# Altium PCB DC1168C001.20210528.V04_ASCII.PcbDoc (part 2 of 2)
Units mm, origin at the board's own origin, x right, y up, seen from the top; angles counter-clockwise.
Board outline 94.98 x 78.49 mm, 2 copper layers (Top Layer, Bottom Layer); 113 components, 100 nets, 347 pads, 214 vias.
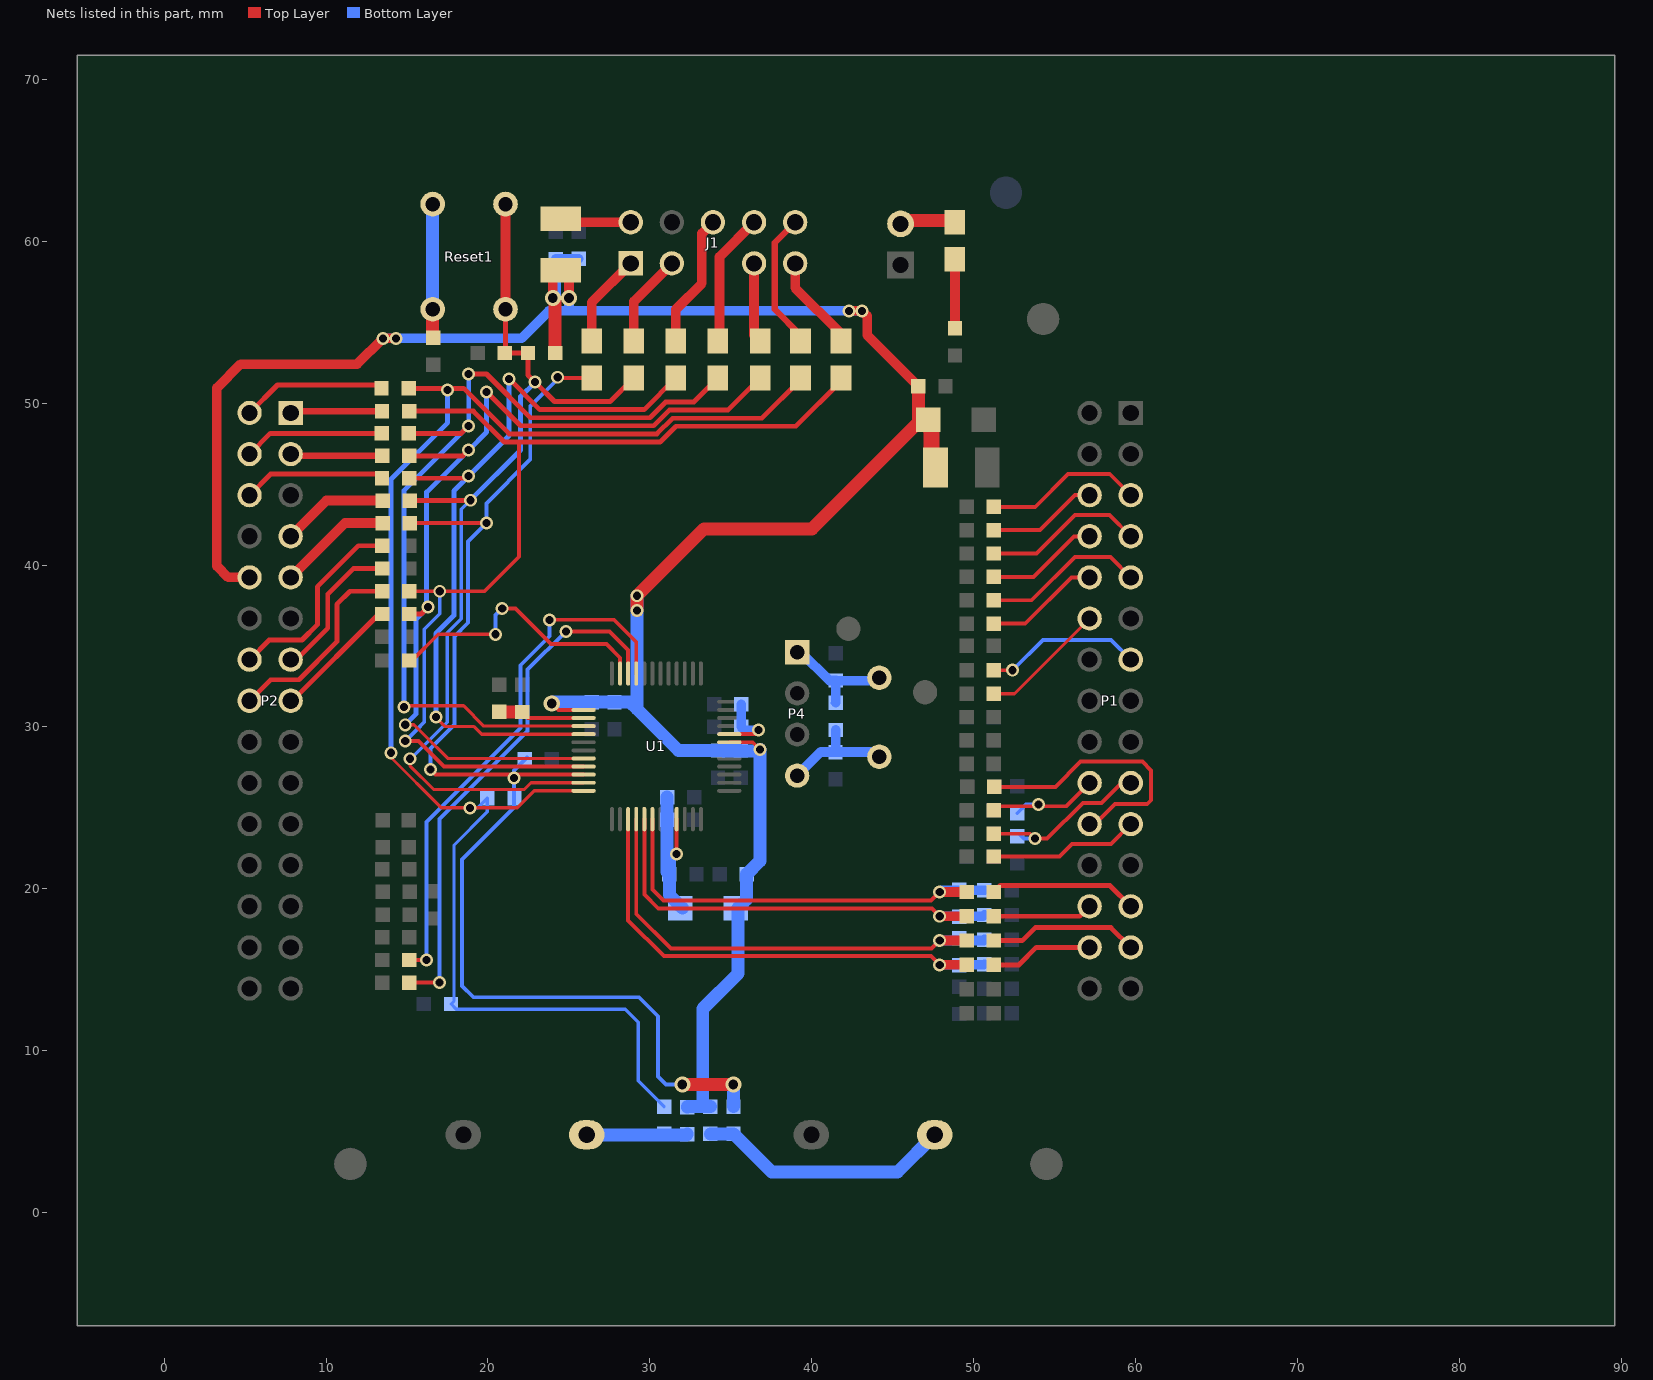
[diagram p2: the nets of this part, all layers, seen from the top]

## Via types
v1: diameter 0.8, hole 0.5, Top Layer to Bottom Layer, tented both sides, 209 vias
v2: diameter 1, hole 0.6, Top Layer to Bottom Layer, tented both sides, 5 vias

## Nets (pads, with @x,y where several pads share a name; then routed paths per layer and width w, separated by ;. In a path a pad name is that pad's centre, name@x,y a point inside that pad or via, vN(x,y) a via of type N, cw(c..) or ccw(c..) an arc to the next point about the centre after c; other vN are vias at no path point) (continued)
IV+: C23.1 C25.1 R46.1 U1.3 | length 30.8
  Top Layer w0.24: U1.3@28.658,24.3 28.658,18.05 30.868,15.84 47.368,15.84 v1(47.908,15.3)
  Top Layer w0.6: v1(47.908,15.3) R46.1@49.308,15.3
  Bottom Layer w0.6: v1(47.908,15.3) 50.63,15.3 C23.1@50.67,15.34
IV-: C25.2 C30.1 R49.1 U1.4 | length 30.1
  Top Layer w0.24: U1.4@29.158,24.3 29.158,18.45 31.308,16.3 47.408,16.3 v1(47.908,16.8)
  Top Layer w0.6: v1(47.908,16.8) R49.1@49.57,16.8
  Bottom Layer w0.6: v1(47.908,16.8) 50.61,16.8 C30.1@50.67,16.86
IVS+: P1.28 R46.2 | length 6.4
  Top Layer w0.3: R46.2@51.246,15.3 52.808,15.3 53.883,16.375 P1.28@57.17,16.375
IVS-: P1.27 R49.2 | length 9.3
  Top Layer w0.3: R49.2@51.246,16.8 53.008,16.8 53.808,17.6 58.485,17.6 P1.27@59.71,16.375
IW+: C21.1 C26.1 R47.1 U1.5 | length 29.1
  Top Layer w0.24: U1.5@29.658,24.3 29.658,19.64 30.518,18.78 47.428,18.78 v1(47.908,18.3) ; 48.408,18.3 R47.1@49.57,18.3
  Top Layer w0.6: v1(47.908,18.3) R47.1@49.57,18.3
  Bottom Layer w0.6: v1(47.908,18.3) 50.59,18.3 C21.1@50.67,18.38
IW-: C26.2 C31.1 R53.1 U1.6 | length 27.1
  Top Layer w0.24: U1.6@30.158,24.3 30.158,19.95 30.838,19.27 47.378,19.27 v1(47.908,19.8)
  Top Layer w0.6: v1(47.908,19.8) R53.1@49.57,19.8
  Bottom Layer w0.6: v1(47.908,19.8) 48.008,19.9 C31.1@50.67,19.9
IWS+: P1.26 R47.2 | length 6.2
  Top Layer w0.3: R47.2@51.246,18.3 56.555,18.3 P1.26@57.17,18.915
IWS-: P1.25 R53.2 | length 9.2
  Top Layer w0.3: R53.2@51.246,19.7 R53.2@51.296,19.75 ; R53.2@51.246,19.8 51.646,20.2 58.425,20.2 P1.25@59.71,18.915
NetD3_1: "LED SW1.2" D3.1 | length 2.6
  Top Layer w0.8: 45.69,61.275 D3.1@48.247,61.275
NetD3_2: D3.2 R39.2 | length 4.1
  Top Layer w0.6: R39.2@48.85,54.618 D3.2@48.85,58.702
NetJ1_1: J1.1 R43.1 | length 5.8
  Top Layer w0.6: R43.1@26.408,53.843 26.408,56.223 J1.1@28.82,58.635
NetJ1_2: J1.2 R6.2 | length 4.4
  Top Layer w0.6: R6.2@24.858,61.4 24.908,61.35 24.733,61.175 J1.2@28.82,61.175
NetJ1_3: J1.3 R29.1 | length 5.8
  Top Layer w0.6: R29.1@29.008,53.843 29.008,56.283 J1.3@31.36,58.635
NetJ1_6: J1.6 R37.2 | length 8.3
  Top Layer w0.6: R37.2@31.608,53.843 31.608,55.8 33.208,57.4 33.208,60.483 J1.6@33.9,61.175
NetJ1_7: J1.7 R41.1 | length 4.4
  Top Layer w0.6: R41.1@36.44,54.211 J1.7@36.44,58.635
NetJ1_8: J1.8 R48.2 | length 7.7
  Top Layer w0.6: R48.2@34.308,54.343 34.308,59.043 J1.8@36.44,61.175
NetJ1_9: J1.9 R50.1 | length 5.5
  Top Layer w0.6: J1.9@38.98,58.635 38.98,57.128 R50.1@41.808,54.3
NetJ1_10: J1.10 R55.2 | length 8.2
  Top Layer w0.4: J1.10@38.98,61.175 37.708,59.903 37.708,55.8 R55.2@39.308,54.2
NetJP1_1: JP1.1 R13.1 R15.1 | length 15.8
  Bottom Layer w0.8: R13.1@33.74,4.862 R15.1@35.17,4.862 37.532,2.5 45.3,2.5 JP1.1@47.6,4.8
NetJP2_1: JP2.1 R22.2 R24.1 | length 6.2
  Bottom Layer w0.8: JP2.1@26.1,4.8 32.274,4.8 R22.2@32.31,4.836
NetP2_1: P2.1 R9.1 | length 5.7
  Top Layer w0.3: P2.1@7.81,49.395 P2.1@7.925,49.51
  Top Layer w0.4: P2.1@7.925,49.51 R9.1@13.45,49.51
NetP2_2: P2.2 R38.2 | length 9
  Top Layer w0.3: P2.2@5.27,49.395 6.995,51.12 13.21,51.12 R38.2@13.42,50.91
NetP2_3: P2.3 R36.1 | length 5.7
  Top Layer w0.4: P2.3@7.81,46.855 7.925,46.74 R36.1@13.47,46.74
NetP2_4: P2.4 R12.2 | length 8.7
  Top Layer w0.3: P2.4@5.27,46.855 6.545,48.13 R12.2@13.43,48.13
NetP2_6: P2.6 R34.2 | length 8.8
  Top Layer w0.3: P2.6@5.27,44.315 6.575,45.62 13.19,45.62 R34.2@13.45,45.36
NetP2_7: P2.7 R32.1 | length 6.6
  Top Layer w0.6: P2.7@7.81,41.775 10.015,43.98 R32.1@13.49,43.98
NetP2_9: P2.9 R30.1 | length 7.1
  Top Layer w0.6: P2.9@7.81,39.235 11.165,42.59 R30.1@13.49,42.59
NetR33_2: R33.2 Reset1.2 | length 8.3
  Top Layer w0.8: R33.2@16.57,54.038 16.583,54.051 Reset1.2@16.583,55.798
  Bottom Layer w0.8: Reset1.2@16.583,55.798 Reset1.2@16.583,62.298
NetR56_2: R56.2 U1.35 | length 17.3
  Top Layer w0.24: R56.2@15.138,34.1 15.31,34.1 16.93,35.72 v1(20.47,35.72) ; v1(20.88,37.31) 21.69,37.31 23.89,35.11 27.317,35.11 28.158,34.269 U1.35@28.158,33.3
  Bottom Layer w0.24: v1(20.47,35.72) 20.47,36.9 v1(20.88,37.31)
NetR57_2: R57.2 U1.34 | length 32.6
  Top Layer w0.24: R57.2@15.146,14.2 v1(17,14.2) ; v1(24.808,35.9) 27.508,35.9 28.658,34.75 U1.34@28.658,33.3
  Bottom Layer w0.24: v1(17,14.2) 17,24.3 22.448,29.748 22.448,33.54 v1(24.808,35.9)
NetR58_2: R58.2 U1.33 | length 33.1
  Top Layer w0.24: R58.2@15.146,15.6 v1(16.2,15.6) ; v1(23.8,36.6) 23.82,36.62 27.788,36.62 29.158,35.25 U1.33@29.158,33.3
  Bottom Layer w0.24: v1(16.2,15.6) 16.2,24.122 22.008,29.93 22.008,33.808 23.8,35.6 v1(23.8,36.6)
PROG: C39.1 C44.2 R24.2 R38.1 R55.1 U1.48 | length 97.5
  Top Layer w0.2: v1(14.01,28.4) 14.01,28.11 17.12,25 v1(18.9,25) 21.808,25 22.858,26.05 U1.48@25.908,26.05
  Top Layer w0.3: R38.1@15.096,50.91 18.498,50.91 21.308,48.1 30.436,48.1 31.406,49.07 36.921,49.07 39.308,51.457 R55.1@39.308,51.557
  Bottom Layer w0.2: v1(18.9,25) 19.362,25 C44.2@19.962,25.6 19.962,24.762 17.9,22.7 17.9,13.062 C39.1@17.718,12.88 18.045,12.553 28.488,12.553 29.28,11.761 29.28,8.138 R24.2@30.88,6.538
  Bottom Layer w0.3: v1(14.01,28.4) 14.01,45.298 14.008,45.3 17.508,48.8 v1(17.508,50.8)
PWM_PFC_1: P1.13 R16.1 | length 9.7
  Top Layer w0.24: R16.1@51.246,33.5 v1(52.408,33.5)
  Bottom Layer w0.24: v1(52.408,33.5) 54.278,35.37 58.495,35.37 P1.13@59.71,34.155
RESETN: C15.1 R14.1 R29.2 R32.2 Reset1.1 U1.47 | length 62.1
  Top Layer w0.2: v1(15.19,28.03) 15.19,27.58 16.64,26.13 22.238,26.13 22.658,26.55 U1.47@25.908,26.55
  Top Layer w0.3: R32.2@15.166,43.98 18.888,43.98 v1(18.908,44) ; C15.1@21.046,53.263 C15.1@21.083,53.3 ; C15.1@21.083,53.125 C15.1@21.083,53.3 ; Reset1.1@21.083,55.798 C15.1@21.083,53.3 ; C15.1@21.183,53.1 R14.1@22.47,53.1 ; C15.1@21.183,53.2 C15.1@21.083,53.3 ; R14.1@22.47,53.2 22.47,51.738 v1(22.908,51.3) 24.108,50.1 27.551,50.1 R29.2@29.008,51.557
  Top Layer w0.6: Reset1.1@21.083,55.798 Reset1.1@21.083,62.298
  Bottom Layer w0.2: v1(15.19,28.03) 15.22,28.03 17.48,30.29 17.48,35.81 18.35,36.68 18.35,43.442 v1(18.908,44)
  Bottom Layer w0.3: v1(18.908,44) 22.008,47.1 22.008,50.4 v1(22.908,51.3)
RUN: P1.12 R23.1 | length 7.8
  Top Layer w0.2: R23.1@51.248,32.052 52.527,32.052 P1.12@57.17,36.695
RXD: R34.1 R37.1 U1.41 | length 48
  Top Layer w0.2: v1(16.78,30.6) 17.36,30.02 19.14,30.02 19.61,29.55 U1.41@25.908,29.55
  Top Layer w0.3: R34.1@15.126,45.36 18.668,45.36 v1(18.808,45.5) ; v1(21.307,51.499) 23.207,49.6 29.651,49.6 R37.1@31.608,51.557
  Bottom Layer w0.3: v1(16.78,30.6) 16.78,35.77 17.9,36.89 17.9,44.592 v1(18.808,45.5) 21.307,47.999 v1(21.307,51.499)
SPI_CS_CLK: P2.13 R21.1 | length 9.2
  Top Layer w0.3: P2.13@7.81,34.155 8.16,34.155 10.1,36.095 10.1,38.2 11.682,39.782 R21.1@13.472,39.782
SPI_FRM_0: P2.14 R20.1 | length 12.5
  Top Layer w0.3: P2.14@5.27,34.155 6.48,35.365 8.51,35.365 9.46,36.315 9.46,38.66 11.986,41.186 R20.1@13.472,41.186
SPI_MISO: P2.15 R19.1 | length 7.9
  Top Layer w0.3: P2.15@7.81,31.615 7.91,31.615 13.268,36.973 R19.1@13.472,36.973
SPI_MOSI: P2.16 R18.1 | length 12.4
  Top Layer w0.3: P2.16@5.27,31.615 6.57,32.915 8.327,32.915 10.67,35.258 10.67,37.57 11.478,38.378 R18.1@13.472,38.378
SWCK: R9.2 R18.2 R50.2 U1.45 | length 66.3
  Top Layer w0.24: v1(14.89,29.12) 15.71,29.12 17.28,27.55 U1.45@25.908,27.55 ; R9.2@15.126,49.51 R9.2@15.356,49.28 ; R18.2@15.148,38.378 v1@17.208,38.378 ; v1(17.02,38.38) 19.78,38.38 21.908,40.508 21.908,47.6
  Top Layer w0.3: R9.2@15.126,49.51 19.098,49.51 21.008,47.6 30.643,47.6 31.613,48.57 39.021,48.57 41.808,51.357 R50.2@41.808,51.557
  Bottom Layer w0.24: v1(14.89,29.12) 15.18,29.41 15.188,29.41 15.61,29.832 15.61,29.84 16.06,30.29 16.06,36.03 17.02,36.99 v1(17.02,38.38)
SWD/TMS: R19.2 R36.2 R41.2 U1.44 | length 58.7
  Top Layer w0.2: v1(14.89,30.13) 15.43,30.13 16.11,29.45 17.51,28.05 U1.44@25.908,28.05
  Top Layer w0.3: R36.2@15.146,46.74 18.448,46.74 v1(18.808,47.1) ; R19.2@15.148,36.973 15.873,36.973 v1(16.3,37.4) ; v1(19.908,50.7) 22.008,48.6 30.229,48.6 31.199,49.57 34.821,49.57 R41.2@36.808,51.557
  Bottom Layer w0.3: v1(14.89,30.13) 15.56,30.8 15.56,36.66 16.208,37.308 16.208,44.5 v1(18.808,47.1) 19.908,48.2 v1(19.908,50.7)
TRSTN: C38.1 C44.1 R15.2 R30.2 R43.2 U1.46 | length 82.5
  Top Layer w0.24: R30.2@15.166,42.59 19.898,42.59 v1(19.908,42.6) ; v1(16.45,27.36) 16.76,27.05 v1@21.6,27.05 ; v1(21.6,26.83) 21.82,27.05 U1.46@25.908,27.05 ; v1(24.308,51.6) 24.351,51.557 R43.2@26.408,51.557
  Top Layer w0.8: v2(32.01,7.91) v2(35.16,7.91)
  Bottom Layer w0.24: v1(16.45,27.36) 16.45,28.666 17.92,30.136 17.92,35.58 18.77,36.43 18.77,41.462 v1(19.908,42.6) 19.908,43.81 22.608,46.51 22.608,49.8 24.308,51.5 v1(24.308,51.6) ; v1(21.6,26.83) 21.6,27.298 C38.1@22.402,28.1 ; v1@21.608,26.7 21.608,25.008 18.4,21.8 18.4,14 19.1,13.3 29.334,13.3 30.51,12.124 30.51,8.39 30.99,7.91 v2(32.01,7.91)
  Bottom Layer w0.8: R15.2@35.17,6.538 v2@35.17,7.9
TXD: R12.1 R48.1 U1.40 | length 55.3
  Top Layer w0.2: v1(14.81,31.23) 14.88,31.3 18.49,31.3 19.74,30.05 U1.40@25.908,30.05
  Top Layer w0.3: R12.1@15.106,48.13 18.338,48.13 v1(18.808,48.6) ; v1(18.808,51.8) 19.908,51.8 22.608,49.1 30.008,49.1 30.978,50.07 32.721,50.07 R48.1@34.208,51.557
  Bottom Layer w0.3: v1(14.81,31.23) 14.81,44.598 14.808,44.6 v1(18.808,48.6) v1(18.808,51.8)
UH_IO20: P1.10 R8.1 | length 7.1
  Top Layer w0.24: R8.1@51.248,36.381 53.189,36.381 56.043,39.235 P1.10@57.17,39.235
UL_IO21: P1.9 R7.1 | length 10.3
  Top Layer w0.24: R7.1@51.42,37.995 R7.1@51.248,37.824 53.589,37.824 56.26,40.495 58.45,40.495 P1.9@59.71,39.235
VCAP12: C5.1 C20.1 C42.1 C43.1 U1.20 U1.39 | length 9.8
  Top Layer w0.2: v1@36.458,29.55 v1(36.708,29.8)
  Top Layer w0.24: C43.1@22.11,30.922 22.482,30.55 U1.39@25.908,30.55 ; U1.20@34.908,29.55 v1@36.458,29.55
  Top Layer w0.8: C42.1@20.7,30.922 C43.1@22.11,30.922
  Bottom Layer w0.6: C5.1@35.646,31.4 C20.1@35.646,30 35.846,29.8 v1(36.708,29.8)
VDA: C1.1 C2.1 C28.2 L1.2 U1.9 | length 10.7
  Top Layer w0.24: v1(31.658,22.15) U1.9@31.658,24.3
  Bottom Layer w0.8: C1.1@31.072,25.662 C2.1@31.072,24.265 31.072,21.036 C28.2@31.208,20.9 ; 31.208,22.15 C28.2@31.208,20.9 ; L1.2@32.017,18.8 31.208,19.609 C28.2@31.208,20.9
VDD: C3.1 C4.2 C6.1 C7.1 C8.1 C9.1 C27.2 C32.1 C33.1 L1.1 P2.10 R6.1 R13.2 R14.2 R22.1 R51.2 U1.19 U1.38 | length 156.2
  Top Layer w0.24: v2(23.94,31.45) 24.34,31.05 U1.38@25.908,31.05 ; U1.19@34.908,29.05 36.358,29.05 v1(36.808,28.6)
  Top Layer w0.6: P2.10@5.27,39.235 3.953,39.235 3.248,39.94 3.248,50.94 4.718,52.41 11.918,52.41 v1(13.508,54) v1(14.308,54) ; v2(24.008,56.5) R6.1@24.008,58.1 ; v2(25.008,56.5) R6.1@25.008,58.1 ; v1(42.308,55.7) v1(43.108,55.7) 43.43,55.378 43.43,54.202 C33.1@46.592,51.04 ; R51.2@47.4,46.475 R51.2@47.636,46.239 ; R51.2@47.636,46.039 R51.2@47.636,46.239 ; R51.2@47.65,46.225 R51.2@47.636,46.239
  Top Layer w0.8: R14.2@24.146,53.2 v2@24.146,56.362 ; v1(29.208,37.2) v1(29.208,38.1) 33.338,42.23 40.01,42.23 46.592,48.812 C33.1@46.592,51.04
  Top Layer w1: C32.1@47.2,48.592 C32.1@47.2,48.965 ; R51.2@47.4,46.475 C32.1@47.4,48.965
  Bottom Layer w0.6: v1(13.508,54) 22.073,54 23.773,55.7 24.208,55.7 ; 25.008,58.822 v2(25.008,56.5) 25.008,55.7 ; C3.1@25.596,58.922 24.208,58.922 24.208,55.7 ; v1(43.108,55.7) 25.008,55.7 ; 24.208,55.7 25.008,55.7
  Bottom Layer w0.8: v2(23.94,31.45) 23.94,31.456 24.012,31.528 C9.1@26.414,31.528 C8.1@27.819,31.528 28.78,31.528 29.208,31.1 ; v1(29.208,38.1) v1(29.208,37.2) 29.208,31.1 ; R22.1@32.31,6.513 32.335,6.538 R13.2@33.74,6.538 ; 33.268,6.73 33.268,12.578 35.446,14.756 35.446,18.8 L1.1@35.746,19.1 ; C6.1@34.546,28.5 36.708,28.5 v1(36.808,28.6) 36.808,21.724 C27.2@35.984,20.9 L1.1@35.984,19.338 ; C7.1@35.608,28.538 C6.1@34.208,28.538 31.77,28.538 29.208,31.1
VH_IO22: P1.8 R5.1 | length 7
  Top Layer w0.24: R5.1@51.248,39.266 53.691,39.266 56.191,41.766 57.161,41.766 P1.8@57.17,41.775
VL_IO23: P1.7 R4.1 | length 10.3
  Top Layer w0.24: R4.1@51.452,40.505 R4.1@51.248,40.709 53.884,40.709 56.275,43.1 58.385,43.1 P1.7@59.71,41.775
VOLT_U: C36.1 P1.19 R31.1 | length 11.1
  Top Layer w0.24: R31.1@51.248,23.398 53.502,23.398 v1(53.8,23.1) 54.545,23.1 56.75,25.305 57.91,25.305 59.14,26.535 P1.19@59.71,26.535
  Bottom Layer w0.24: C36.1@52.8,23.4 53.1,23.1 v1(53.8,23.1)
VOLT_V: C40.1 P1.20 R35.1 | length 8.1
  Top Layer w0.24: R35.1@51.248,24.845 51.503,25.1 55.735,25.1 P1.20@57.17,26.535
  Bottom Layer w0.24: C40.1@52.7,24.662 53.238,25.2 v1(54,25.2)
VOLT_W: P1.22 R40.1 | length 16.8
  Top Layer w0.24: R40.1@51.288,26.295 55.05,26.295 56.61,27.855 60.43,27.855 60.97,27.315 60.97,25.465 60.73,25.225 58.74,25.225 57.51,23.995 P1.22@57.17,23.995
VSP: P1.21 R28.1 | length 9.3
  Top Layer w0.24: R28.1@51.248,21.995 55.31,21.995 56.08,22.765 58.48,22.765 P1.21@59.71,23.995
WH_IO24: P1.6 R2.1 | length 7.3
  Top Layer w0.24: R2.1@51.248,42.152 54.107,42.152 56.27,44.315 P1.6@57.17,44.315 P1.6@56.833,44.652
WL_IO25: P1.5 R1.1 | length 9.8
  Top Layer w0.24: R1.1@51.248,43.595 53.81,43.595 55.83,45.615 58.41,45.615 P1.5@59.71,44.315
XIN: C34.2 P4.4 R3.1 Y1.1 | length 7.2
  Bottom Layer w0.6: P4.4@39.1,26.99 40.553,28.443 C34.2@41.466,28.443 ; R3.1@41.486,29.81 41.486,28.463 C34.2@41.466,28.443 ; Y1.1@44.176,28.155 43.888,28.443 C34.2@41.466,28.443
XIO: C35.2 P4.1 R3.2 Y1.2 | length 7.6
  Bottom Layer w0.2: R3.2@41.278,31.486 41.355,31.409 R3.2@41.355,31.355
  Bottom Layer w0.24: R3.2@41.278,31.486 R3.2@41.486,31.486
  Bottom Layer w0.6: P4.1@39.1,34.61 39.35,34.61 41.093,32.867 C35.2@41.496,32.867 ; R3.2@41.486,31.486 41.486,32.857 43.998,32.857 Y1.2@44.176,33.035
pads on no net: P2.5 P2.28

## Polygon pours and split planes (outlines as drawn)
GND on Top Layer "Bottom Layer-W" (hatched 90Degree grid 0.2 track 0.2, remove dead copper, pour order 26): 17.3,18.5 18,19.2 18.2,19.4 19.4,19.4 20.2,19.4 20.5,19.1 20.5,18.4 20.5,18.2 19.9,17.6 19.7,17.4 17.6,17.4 17.362,17.4 16.6,18.162
GND on Top Layer "Bottom Layer-No Net 1" (hatched 90Degree grid 0.2 track 0.2, remove dead copper, pour order 36): 25.107,33.98 16.71,33.98 15.88,33.15 14.97,33.15 13.2,33.15 10.85,30.8 9.26,29.21 9.26,25.56 11,25.56 12.82,27.38 13.2,27.76 13.2,28.57 14.26,29.63 14.26,31.37 14.49,31.6 14.73,31.84 15.53,31.84 19.79,31.84 20.29,32.34 23.38,32.34 25.6,32.34 25.9,32.64
GND on Top Layer "Bottom Layer-No Net 1" (hatched 90Degree grid 0.2 track 0.2, remove dead copper, pour order 32): 40.47,24.25 46.51,24.25 47.12,24.86 47.12,26.18 47.12,30.26 48.03,31.17 48.03,33.37 48.03,34.54 47.06,35.51 44.98,37.59 41,37.59 37.15,37.59 34.74,35.18 34.74,32.65 35.21,32.18 36.88,32.18 37.61,32.91 37.61,36.04 37.87,36.3 40.01,36.3 40.42,35.89 40.51,35.8 40.51,31.24 40.51,26.31 39.78,25.58 39.78,25.4 39.78,24.95 40.1,24.63
GND on Top Layer "Bottom Layer-No Net 1" (hatched 90Degree grid 0.2 track 0.2, remove dead copper, pour order 6): 23.97,39.6 29.608,39.6 31.308,41.3 33.088,43.08 39.288,43.08 45.06,48.852 45.06,50.76 44.65,51.17 44.3,51.17 43.808,50.678 43.808,50.3 43.108,49.6 41.008,49.6 41.008,49.5 40.108,48.6 39.508,48 32.908,48 31.708,48 30.708,47 29.008,47 23.408,47 22.508,46.1 22.508,41.062
GND on Top Layer "Bottom Layer-No Net 1" (hatched 90Degree grid 0.2 track 0.2, remove dead copper, pour order 8): 9.708,27.388 10.47,28.15 13.45,28.15 16.9,24.7 21.808,24.7 22.408,25.3 22.908,25.8 24.508,25.8 24.708,25.6 25.208,25.1 25.208,24.4 25.108,24.3 22.408,21.6 17.858,21.6 15.928,23.53 8.238,23.53 9.708,25
GND on Top Layer "Bottom Layer-No Net 1" (hatched 90Degree grid 0.2 track 0.2, remove dead copper, pour order 12): 49.82,51.888 44.208,57.5 43.908,57.8 43.608,58.1 43.608,60.3 43.608,62.942 42.35,64.2 38.608,64.2 31.508,64.2 30.808,63.5 30.408,63.1 30.408,62.2 30.408,61 30.708,60.7 30.908,60.5 31.308,60.5 31.708,60.5 31.908,60.7 32.208,61 32.208,61.5 32.208,61.9 32.608,62.3 32.708,62.4 33.808,62.4 39.508,62.4 40.108,61.8 40.108,60.6 40.108,57.2 41.008,56.3 41.208,56.1 43.2,56.1 48.26,51.04 49.82,51.04
GND on Top Layer "Bottom Layer-No Net 1" (hatched 90Degree grid 0.2 track 0.2, remove dead copper, pour order 14): 19.37,53.1 20.008,53.738 20.008,56 20.008,63.2 19.708,63.5 19.008,63.5 18.308,63.5 17.908,63.5 16.208,61.8 14.208,59.8 14.208,57.7 14.208,53.1 13.47,52.362 13.532,52.3 17.008,52.3 17.308,52.3 17.808,52.8 18.108,53.1 19.37,53.1
GND on Top Layer "Bottom Layer-No Net 1" (hatched 90Degree grid 0.2 track 0.2, remove dead copper, pour order 16): 7.608,11.3 17.708,1.2 47.408,1.2 57.508,11.3 63.908,11.3 64.808,12.2 64.808,51.012 62.41,53.41 52.73,53.41 52.48,53.66 52.48,64.31 50.49,66.3 13.108,66.3 12.108,66.3 11.808,66 11.208,65.4 11.208,59.2 10.308,58.3 7.208,55.2 1.308,55.2 0.808,54.7 0.208,54.1 0.208,12.6 0.408,12.4 1.508,12.4 3.008,13.9 3.808,14.7 3.808,22.4 4.308,22.9 4.808,23.4 5.308,23.4 5.208,23.5 4.808,23.9 4.808,24.5 3.108,26.2 1.608,27.7 1.608,51.8 2.708,52.9 3.808,54 8.608,54 11.508,56.9 12.508,57.9 12.508,63.1 13.208,63.8 14.708,65.3 48.008,65.3 48.16,65.3 51.09,62.37 51.09,53.18 52.37,51.9 62.408,51.9 63.608,50.7 63.608,47.6 62.808,46.8 61.408,45.4 61.408,30.6 61.008,30.2 60.608,29.8 59.408,29.8 59.108,29.5 59.108,28.9 59.408,28.6 59.408,28.5 61.108,28.5 61.508,28.1 61.508,23.2 60.808,22.5 60.408,22.1 56.908,22.1 56.808,22 56.508,21.7 56.508,21.2 56.708,21 56.908,20.8 60.008,20.8 61.308,19.5 61.308,13.1 61.008,12.8 60.408,12.2 52.808,12.2 52.408,11.8 51.908,11.3 32.708,11.3 26.908,17.1 20.708,17.1 18.908,15.3 18.908,13.2 18.608,12.9 17.668,11.96 12.748,11.96 11.708,13 10.308,14.4 4.508,14.4 4.008,13.9 3.308,13.2 3.308,11.3
GND on Top Layer "Bottom Layer-No Net 1" (hatched 90Degree grid 0.2 track 0.2, remove dead copper, pour order 18): 3.608,15.699 5.108,14.199 5.108,14.099 5.108,13.1 3.308,11.3 1.108,11.3 0.608,11.8 0.5,11.908 0.5,13.099
GND on Top Layer "Bottom Layer-No Net 1" (hatched 90Degree grid 0.2 track 0.2, remove dead copper, pour order 39): 32.698,13.61 44.398,13.61 44.798,14.01 44.908,14.12 44.908,14.43 44.908,14.85 44.448,15.31 44.318,15.44 42.658,15.44 32.618,15.44 32.198,15.02 32.188,15.01 32.188,14.34 32.188,14.15 32.728,13.61
GND on Top Layer "Bottom Layer-No Net 1" (hatched 90Degree grid 0.2 track 0.2, remove dead copper, pour order 41): 31.868,16.57 32.098,16.34 42.768,16.34 44.178,16.34 44.948,17.11 44.948,17.55 44.948,17.89 44.788,18.05 44.368,18.47 43.188,18.47 31.818,18.47 31.528,18.18 31.438,18.09 31.438,17.31 31.438,17.02 31.868,16.59
GND on Top Layer "Bottom Layer-No Net 1" (hatched 90Degree grid 0.2 track 0.2, remove dead copper, pour order 43): 42.7,21.3 42.28,20.88 41.418,20.88 34.398,20.88 33.818,21.46 33.818,22.51 33.818,24.24 34.358,24.78 34.988,25.41 35.748,25.41 39.158,22 42.4,22 42.7,21.7
GND on Top Layer "Bottom Layer-No Net 1" (hatched 90Degree grid 0.2 track 0.2, remove dead copper, pour order 45): 33.818,24.24 33.818,24.82 33.288,25.35 32.968,25.67 32.578,25.67 32.308,25.67 32.138,25.5 31.698,25.94 31.328,25.94 31.228,25.94 30.5,26.668 30.5,27.3 30.7,27.5 32.138,27.5 33.678,25.96 33.918,25.72 34.228,25.41 35.107,25.41
GND on Top Layer "Bottom Layer-No Net 1" (hatched 90Degree grid 0.2 track 0.2, remove dead copper, pour order 47): 27.378,27.71 27.378,31.032 26.85,31.56 26.51,31.56 26.51,31.95 26.35,32.11 25.588,32.11 25.28,32.11 24.218,33.172 24.218,33.46 24.448,33.69 24.738,33.98 25.298,33.98 27.068,33.98 27.168,33.88 27.308,33.74 27.308,33.19 27.308,32.66 27.528,32.44 28.408,31.56 30.248,31.56 32.918,31.56 33.298,31.18 33.298,30.8 33.298,30.46 33.698,30.06 33.478,29.83 33.298,29.65 33.298,28.91 32.958,28.57 32.798,28.41 31.768,28.41 29.088,28.41 28.658,27.98 28.138,27.46 27.678,27.46 27.628,27.46
GND on Top Layer "Bottom Layer-No Net 1" (hatched 90Degree grid 0.2 track 0.2, remove dead copper, pour order 49): 31.709,12.299 31.818,12.19 46.498,12.19 47.678,11.01 47.578,11.11 32.088,11.11
GND on Top Layer "Bottom Layer-No Net 1" (hatched 90Degree grid 0.2 track 0.2, remove dead copper, pour order 51): 26.908,17.1 26.908,21.25 26.588,21.57 25.758,21.57 24.998,21.57 23.918,20.49 18.908,15.48 18.908,14.899 25.217,14.899 26.508,16.19
VDD on Top Layer "Bottom Layer-No Net 1" (hatched 90Degree grid 0.2 track 0.2, remove dead copper, pour order 59): 23.668,58.75 23.498,58.75 23.408,58.84 23.388,58.86 23.178,58.86 23.108,58.86 22.678,58.43 22.628,58.38 22.628,57.28 22.628,54.54 23.808,53.36 23.898,53.27 24.478,53.27 24.478,53.28 24.948,53.75 25.328,54.13 25.328,56.42 25.328,56.43 25.578,56.68 25.628,56.73 25.628,57.78
VDD on Top Layer "Bottom Layer-No Net 1" (hatched 90Degree grid 0.2 track 0.2, remove dead copper, pour order 63): 35.578,29.07 36.948,29.07 37.038,28.98 37.278,28.74 37.278,28.55 37.278,28.13 37.198,28.05 37.128,27.98 36.788,27.98 36.518,27.98 36.268,28.23 35.633,28.865 35.633,29.05
VDA on Top Layer "Bottom Layer-No Net 1" (hatched 90Degree grid 0.2 track 0.2, remove dead copper, pour order 65): 31.668,23.37 31.648,23.37 31.228,22.95 30.948,22.67 30.948,22.26 30.948,21.5 31.458,20.99 31.788,20.99 31.888,20.99 32.218,21.32 32.348,21.45 32.348,22.34 32.348,22.77 31.698,23.42
GND on Bottom Layer "Bottom Layer-No Net 1" (hatched 90Degree grid 0.2 track 0.2, remove dead copper, pour order 34): 7.608,11.3 17.628,1.28 47.488,1.28 57.508,11.3 63.908,11.3 64.5,11.892 64.5,54.808 64.008,55.3 56.26,55.3 53.08,58.48 45.575,65.985 11.793,65.985 11.707,65.899 11.208,65.4 11.208,59.2 9.307,57.299 7.208,55.2 1.308,55.2 0.5,54.392 0.5,11.908 1.108,11.3
GND on Bottom Layer "Bottom Layer-No Net 1" (hatched 90Degree grid 0.2 track 0.2, remove dead copper, pour order 31): 57.208,22.1 59.008,22.1 60.609,22.1 61.608,23.099 61.608,21.699 61.608,19.499 60.307,20.8 59.408,20.8 56.707,20.8 55.307,19.4 55.408,19.501 55.408,23.299 55.409,23.299 56.608,22.1
GND on Bottom Layer "Bottom Layer-No Net 1" (hatched 90Degree grid 0.2 track 0.2, remove dead copper, pour order 33): 55.907,30.3 56.007,30.4 57.808,30.4 57.908,30.4 58.208,30.1 59.409,28.899 59.708,28.899 61.107,28.899 61.307,29.1 61.208,29.199 61.208,29.8 59.408,29.8 58.508,30.7 57.208,32 55.907,32
VDD on Bottom Layer "Bottom Layer-No Net 1" (hatched 90Degree grid 0.2 track 0.2, remove dead copper, pour order 57): 23.538,55.66 23.538,56.92 23.538,59 23.808,59.27 24.118,59.27 25.958,59.27 26.098,59.13 26.228,59 26.228,58.1 26.228,56.11 26.548,55.79 26.468,55.71 24.508,55.71
VDA on Bottom Layer "Bottom Layer-No Net 1" (hatched 90Degree grid 0.2 track 0.2, remove dead copper, pour order 67): 32.488,19.28 32.518,19.31 32.518,19.43 32.518,19.6 32.248,19.87 32.248,21.77 32.248,25.05 31.348,25.95 31.098,25.7 31.098,24.98 31.098,19.6 31.548,19.15
VDD on Bottom Layer "Bottom Layer-No Net 1" (hatched 90Degree grid 0.2 track 0.2, remove dead copper, pour order 69): 23.5,30.9 23.5,31.5 23.5,31.7 23.7,31.9 24.5,31.9 24.728,31.9 25.1,31.528 25.1,31.3 25.1,31.2 24.6,30.7 24.2,30.3 23.8,30.3 23.7,30.3 23.5,30.5 23.5,30.9

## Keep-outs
Keep-Out Layer:
  circle w0.1: c60.5,61.985 r1.6
  circle w0.1: c4.5,61.985 r1.6
  circle w0.1: c4.5,4.485 r1.6
  circle w0.1: c60.5,4.485 r1.6
  lines w0.1: 0,61.983 0,4.492 ccw(c4.502,4.492) 4.502,-0.01 ; 0.005,61.983 cw(c4.507,61.983) 4.507,66.485 60.498,66.485 ; 4.502,-0.015 60.493,-0.015 ccw(c60.493,4.487) 64.995,4.487 ; 60.498,66.48 cw(c60.498,61.978) 65,61.978 65,4.487 ; 64.997,1.98 64.997,32.48

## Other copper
Top Layer:
  rectangle net GND: 5.46,13.24 7.78,14.54
  rectangle net GND: 13.64,23.92 14.86,24.59
  rectangle net GND: 30.65,61.15 32.05,62.699
  rectangle net GND: 48.93,51.54 49.24,52.58
  rectangle net GND: 3.4,23.26 5.24,24.62
  rectangle net GND: 8.01,23.88 9.36,24.54
  rectangle net GND: 57.2,20.79 61.107,22.12
  rectangle net GND: 59.87,28.499 61.109,29.58
Bottom Layer:
  rectangle net GND: 40.45,34.5 41.27,34.98
  rectangle net GND: 30.62,61.15 32.1,62.97
  rectangle net GND: 3.58,41.08 5.31,42.51
  rectangle net GND: 3.12,23.26 9.107,24.699
  rectangle net GND: 3.37,35.96 9.94,37.43
  rectangle net GND: 9.808,26.299 10.4,28.699
  rectangle net GND: 27.908,29.841 28.92,30.29
  rectangle net GND: 12.708,52.499 18.71,53.33
  rectangle net GND: 19.707,14 29.51,14.67
  rectangle net GND: 30.708,14.51 33.66,17.4
  rectangle net GND: 32.37,26.8 33.107,27.46
  rectangle net GND: 30.48,27.34 33.12,27.688
  rectangle net GND: 35.3,22.4 35.908,26.69
  rectangle net GND: 33.793,20.99 34.53,25.699
  rectangle net GND: 31.808,29.73 33.7,31
  rectangle net GND: 51.25,20.8 52.17,21.06

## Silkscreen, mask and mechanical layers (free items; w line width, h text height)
Top Overlay:
  drawing of 1553 lines, arcs and shapes, not listed
  text "IO40" at 38.71,66.25 h1 r270
  text "VDD" at 28.378,65.63 h1.3 r270
  text "GND" at 30.944,65.631 h1.3 r270
  text "RXD" at 33.482,65.631 h1.3 r270
  text "TXD" at 36.033,65.631 h1.3 r270
  text "NC" at 33.138,58.16 h1.3
  text "TRSTn" at 25.808,55.8 h1.3
  text "IO30" at 44,55.8 h1.5
  text "SWD" at 35.21,55.755 h1.3
  text "SWCK" at 38.27,55.755 h1.3
  text "RESETN" at 29.808,55.6 h1.3
  text "2" at 4.578,51.22 h2
  text "1" at 7.378,51.22 h2
  text "2" at 56.478,51.22 h2
  text "1" at 59.278,51.22 h2
  text "IO40" at 0.358,49.05 h1
  text "GND" at 52.258,49.05 h1
  text "IO39" at 9.358,48.96 h1
  text "GND" at 61.588,48.96 h1
  text "IO34" at 0.358,46.505 h1
  text "3.3V" at 52.258,46.505 h1
  text "IO38" at 9.358,46.44 h1
  text "3.3V" at 61.588,46.44 h1
  text "NC" at 9.6,45 h1.5 r270
  text "RESETN" at 11.548,43.98 h1.3 r270
  text "IO35" at 0.358,43.961 h1
  text "IO24" at 52.258,43.961 h1
  text "IO25" at 61.588,43.9 h1
  text "GND" at 0.358,41.416 h1
  text "IO22" at 52.258,41.416 h1
  text "IO23" at 61.588,41.36 h1
  text "XIO" at 38.397,41.324 h1.6
  text "TRSTn" at 10.268,41.14 h1.3 r270
  text "IO17" at 38.397,39.849 h1.6
  text "VDD" at 0.358,38.871 h1
  text "IO20" at 52.258,38.871 h1
  text "IO21" at 61.588,38.82 h1
  text "IO16" at 38.397,38.373 h1.6
  text "XIN" at 38.397,36.88 h1.6
  text "GND" at 0.358,36.327 h1
  text "IO18" at 52.258,36.327 h1
  text "IO19" at 61.558,36.14 h1
  text "GND" at 9.358,36.1 h1
  text "AD15" at 52.2,34 h1
  text "IO37" at 0.358,33.782 h1
  text "IO36" at 9.358,33.67 h1
  text "IO26" at 61.558,33.61 h1
  text "IO39" at 0.358,31.237 h1
  text "GND" at 52.258,31.237 h1
  text "IO38" at 9.358,31.14 h1
  text "AD14" at 61.2,31.1 h1
  text "IO30" at 0.358,28.693 h1
  text "AD6" at 52.258,28.693 h1
  text "IO29" at 9.358,28.365 h1
  text "GND" at 61.56,28.365 h1
  text "3.3V" at 0.358,26.148 h1
  text "AD12" at 52.258,26.148 h1
  text "3.3V" at 9.358,25.825 h1
  text "AD10" at 61.56,25.825 h1
  text "GND" at 0.358,23.604 h1
  text "AD8" at 52.258,23.604 h1
  text "GND" at 9.358,23.265 h1
  text "AD9" at 61.56,23.265 h1
  text "AD11" at 0.358,21.059 h1
  text "GND" at 52.258,21.059 h1
  text "AD13" at 9.358,20.92 h1
  text "GND" at 61.408,20.92 h1
  text "IO27" at 0.358,18.514 h1
  text "AD4" at 52.258,18.514 h1
  text "AD7" at 9.358,18.29 h1
  text "AD5" at 61.558,18.29 h1
  text "AD2" at 52.258,15.97 h1
  text "IO28" at 9.358,15.9 h1
  text "AD3" at 61.508,15.9 h1
  text "GND" at 0.358,13.425 h1
  text "AD0" at 52.258,13.425 h1
  text "GND" at 9.358,13.31 h1
  text "AD1" at 61.528,13.31 h1
  text "29" at 7.198,10.56 h2
  text "29" at 59.098,10.56 h2
  text "30" at 4.358,10.52 h2
  text "30" at 56.258,10.52 h2
  text "DC1168C001.20210528.V04" at 10.1,9.1 h3
  text "GPIO0" at 20.307,7.3 h1.5
  text "NORMAL" at 36.2,7.099 h1.2
  text "DEBUG" at 47.107,7.1 h1.2
  text "NORMAL" at 28.046,4.595 h1.2
  text "ISP" at 13.835,4.3 h1.2
  text "VDD" at 28,3.099 h1
  text "GND" at 13.225,2.81 h1
  text "TRSTN" at 41.6,1.699 h1.5
  text "GND" at 37.7,1.5 h1
  text "VDD" at 47.107,1.5 h1
Bottom Overlay:
  lines w0.1: 51.5,35.1 51.92,34.68 ; 51.92,40.26 51.92,34.68 ; 52.34,35.1 51.92,34.68
Top Solder:
  rectangle: 52.725,53.65 55.85,56.725
  rectangle: 9.925,1.45 13.05,4.525
  rectangle: 52.925,1.45 56.05,4.525
Bottom Solder:
  region: 53.575,64.525 50.45,64.525 50.45,61.45 53.575,61.45
  region: 13.075,4.525 9.95,4.525 9.95,1.45 13.075,1.45
  region: 56.075,4.525 52.95,4.525 52.95,1.45 56.075,1.45
Mechanical 1 (Mech13):
  circle w0.1: c4.5,62 r1.6
  circle w0.1: c60.5,62 r1.6
  circle w0.1: c60.5,4.5 r1.6
  circle w0.1: c4.5,4.5 r1.6
  lines w0.1: -0.001,4.5 ccw(c4.5,4.5) 4.5,-0.001 60.5,-0.001 ccw(c60.5,4.5) 65.001,4.5 ; -0.001,62 cw(c4.5,62) 4.5,66.501 60.5,66.501 cw(c60.5,62) 65.001,62 65.001,4.2 ; 0,4.3 0,62.1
